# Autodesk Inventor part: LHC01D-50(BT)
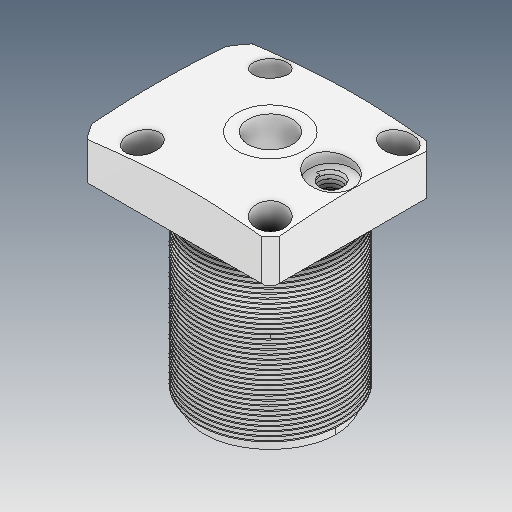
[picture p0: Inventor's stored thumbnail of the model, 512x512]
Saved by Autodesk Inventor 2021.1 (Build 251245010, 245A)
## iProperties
Created: 2021-06
Part Number: LHC01D-50(BT)
Material: Ogólny
Document SubType Name: Modeling
Designer: user
Density: 1 g/cm^3
Appearance: Domyślna
Author: user
Revision Number: ÈÎºÎ
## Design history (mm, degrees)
feature "ÊäÈë1"
node "Bryła1"
